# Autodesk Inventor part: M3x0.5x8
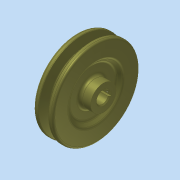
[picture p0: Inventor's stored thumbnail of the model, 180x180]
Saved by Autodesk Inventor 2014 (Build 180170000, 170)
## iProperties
Company: 한국ATC센터
Created: 2009-02
Part Number: M3x0.5x8
Document SubType Name: Modeling
Designer: KYOUNG IL JANG
Density: 7.25 g/cm^3
Mass: 594.655 g
Surface Area: 210.328 cm^2
Volume: 82.0213 cm^3
Material: 주철
Vendor: CBT Solutions
Appearance: 티타늄
Author: KYOUNG IL JANG
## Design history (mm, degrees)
sketch "스케치1"
  geometry: L1 (-13, 0)-(13, 0); L2 (-13, 0)-(-13, 12.5); L3 (-13, 12.5)-(-9, 12.5); L4 (-9, 12.5)-(-9, 23); L5 (-9, 23)-(-13, 27); L6 (-13, 27)-(-13, 42.7); L7 (-13, 42.7)-(-8.325, 42.7); L8 (-8.325, 42.7)-(-5.574, 33.7); L9 (-5.574, 33.7)-(-1.426, 33.7); L10 (-1.426, 33.7)-(1.325, 42.7); L11 (1.325, 42.7)-(6, 42.7); L12 (6, 42.7)-(6, 27); L13 (6, 27)-(2, 23); L14 (2, 23)-(2, 12.5); L15 (2, 12.5)-(13, 12.5); L16 (13, 12.5)-(13, 0); L17 (-7.5, 40)-(0.5, 40); 2 further points
  constraints: 34 end point, 6 parallel, 5 collinear, 5 equal length, 4 perpendicular, 2 point on line, 1 coincident, 1 horizontal, 1 midpoint
  dimensions: "d0" = 26 distance of L1.start L1.end; "d1" = 2.7 distance between parallel lines of L7 L17; "d2" = 6.3 distance between parallel lines of L9 L17; "d3" = 8 distance of L17.start L17.end; "d4" = 34 deg angle of L10 L8; "d5" = 19 distance between parallel lines of L12 L6; "d7" = 25 diameter of L15 L1; "d8" = 46 diameter of L13.end L1; "d9" = 54 diameter of L12.end L1; "d10" = 4 distance between parallel lines of L2 L4; "d11" = 80 diameter of L17 L1
revolve "회전1" sketch "스케치1" stored, may be unused: angle "d12" = 90 deg
sketch "스케치2"
  geometry: L1 (-2, 5.657)-(-2, 7.8); L2 (-2, 7.8)-(2, 7.8); L3 (2, 7.8)-(2, 5.657); A1 r 6 centre (0, 0) between (-2, 5.657) and (2, 5.657); 1 further point
  constraints: 6 end point, 2 parallel, 2 point on circle, 1 centre point, 1 coincident, 1 perpendicular, 1 vertical
  dimensions: "d13" = 12 diameter of A1; "d14" = 13.8 dimension on A1 L2; "d15" = 4 distance of L1.end L2.end
extrude "돌출1" cut sketch "스케치2" stored distance "d16" = 10; taper "d17" = 0 deg
node "작업 평면1"
sketch "스케치3"
  geometry: L1 (-5.5, 12.5)-(-5.5, -12.5) reference; 3 further points
  constraints: 1 horizontal alignment, 1 midpoint
  dimensions: "d18" = 4 distance from line of point (-1.5, 0) L1
hole "구멍1" sketch "스케치3" at (-1.5, 0) diameter "d19" = 2.459; stored, may be unused: countersink angle "d23" = 90 deg, drill point angle "d25" = 118 deg; dims "d20" = 6, "d21" = 4, "d22" = 2, "d24" = 8
fillet "모깎기1" dims "d26" = 2, "d27" = 0.5, "d28" = 1, "d29" = 3
chamfer "모따기1" distance "d30" = 1; stored, may be unused: second distance "d31" = 2, angle "d32" = 45 deg
node "솔리드1"
